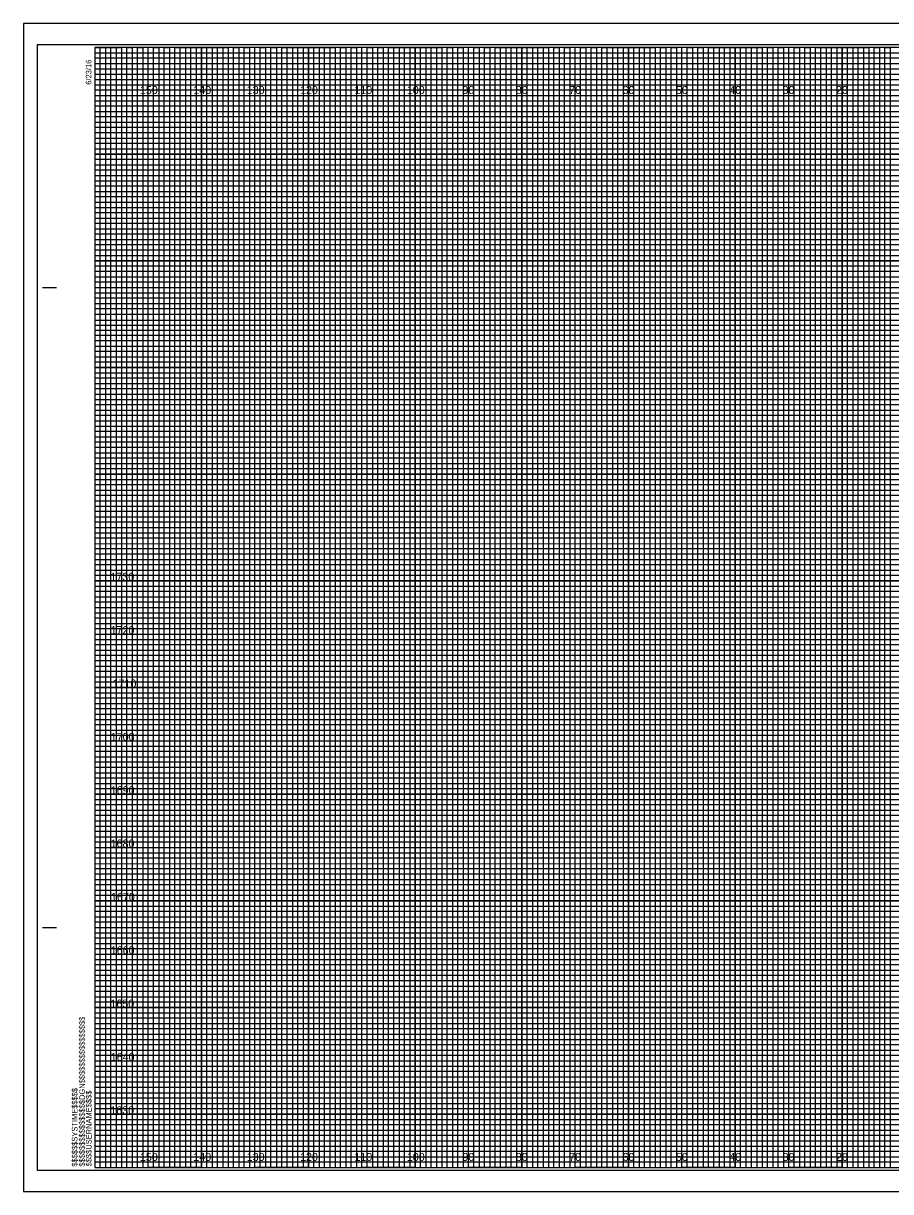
# Model space of a CAD drawing. Extents: x -3334 to 0, y 84 to 12624.
# Drawn here: x -336.5 to -174, y 84.2 to 303.2 of the extents above; entities that cross this region are included whole.
import ezdxf

# ---------------------------------------------------------------- set-up
doc = ezdxf.new("R2010")
doc.units = 0
for name, color, linetype in [('Old_Level_62', 7, 'Continuous'), ('Pattern 1', 7, 'Continuous'), ('Pattern 18', 7, 'Continuous'), ('Pattern 4', 7, 'Continuous'), ('Pattern 5', 7, 'Continuous'), ('Prop Dimension', 7, 'Continuous'), ('Prop Horizontal Alignment', 7, 'Continuous'), ('Raster_Level_0', 7, 'Continuous'), ('Scratch_Level_0', 7, 'Continuous'), ('Scratch_Level_3', 7, 'Continuous'), ('Scratch_Level_5', 7, 'Continuous')]:
    doc.layers.add(name, color=color, linetype=linetype)

msp = doc.modelspace()

# ---------------------------------------------------------------- linework, layer by layer
at = {"layer": 'Old_Level_62'}
for p, q in [((-332.92, 253.67), (-330.42, 253.67)), ((-332.82, 253.67), (-330.32, 253.67)), ((-332.92, 133.67), (-330.42, 133.67)), ((-332.82, 133.67), (-330.32, 133.67)), ((-323.12, 88.67), (-323.12, 88.67)), ((-323.12, 88.67), (-323.12, 88.67)), ((-323.12, 88.67), (-323.12, 88.67)), ((-323.12, 88.67), (-323.12, 88.67)), ((-323.12, 88.67), (-323.12, 88.67)), ((-323.12, 88.67), (-323.12, 88.67)), ((-323.12, 88.67), (-323.12, 88.67))]:
    msp.add_line(p, q, dxfattribs=at)
msp.add_lwpolyline([(-3.12, 298.67), (-323.12, 298.67), (-323.12, 88.67), (-3.12, 88.67)], close=True, dxfattribs=at)
at = {"layer": 'Pattern 18'}
msp.add_lwpolyline([(-336.52, 84.17), (0.18, 84.17), (0.18, 303.17), (-336.52, 303.17)], close=True, dxfattribs=at)
at = {"layer": 'Pattern 4'}
for p, q in [((-323.12, 297.67), (-63.12, 297.67)), ((-63.12, 296.65), (-323.12, 296.65)), ((-323.12, 296.65), (-323.12, 295.67)), ((-323.12, 295.67), (-63.12, 295.67)), ((-63.12, 294.56), (-323.12, 294.56)), ((-323.12, 294.56), (-323.12, 292.67)), ((-323.12, 292.67), (-3.12, 292.67))]:
    msp.add_line(p, q, dxfattribs=at)
for points in [[(-323.12, 291.67), (-53.12, 291.67), (-3.12, 291.67), (-3.12, 290.67), (-323.12, 290.67)], [(-323.12, 289.67), (-3.12, 289.67), (-3.12, 287.67), (-323.12, 287.67)], [(-323.12, 286.67), (-3.12, 286.67), (-3.12, 285.67), (-323.12, 285.65)], [(-323.12, 284.67), (-3.12, 284.67), (-3.12, 282.67), (-323.12, 282.67)], [(-323.12, 281.67), (-3.12, 281.67), (-3.12, 280.67), (-323.12, 280.67)], [(-323.12, 279.67), (-3.12, 279.67), (-3.12, 277.67), (-323.12, 277.67)], [(-323.12, 276.67), (-3.12, 276.67), (-3.12, 275.67), (-323.12, 275.67)], [(-323.12, 274.67), (-3.12, 274.67), (-3.12, 272.67), (-323.12, 272.67)], [(-323.12, 271.67), (-3.12, 271.67), (-3.12, 270.67), (-323.12, 270.67)], [(-323.12, 269.67), (-3.12, 269.67), (-3.12, 267.67), (-323.12, 267.67)], [(-323.12, 266.67), (-3.12, 266.67), (-3.12, 265.67), (-323.12, 265.67)], [(-323.12, 264.67), (-3.12, 264.67), (-3.12, 262.62), (-3.12, 261.67), (-3.12, 260.67), (-323.12, 260.67)], [(-323.12, 262.67), (-3.12, 262.67), (-3.12, 261.67), (-323.12, 261.67)], [(-323.12, 259.67), (-3.12, 259.67), (-3.12, 257.67), (-323.12, 257.7)], [(-323.12, 257.7), (-3.12, 257.67), (-3.12, 256.67), (-323.12, 256.67)], [(-323.12, 255.67), (-3.12, 255.67), (-3.12, 254.67), (-323.12, 254.67)], [(-323.12, 252.67), (-3.12, 252.67), (-3.12, 251.67), (-323.12, 251.67)], [(-323.12, 250.67), (-3.12, 250.67), (-3.12, 249.67), (-323.12, 249.67)], [(-323.19, 247.56), (-3.12, 247.56), (-3.12, 246.55), (-323.19, 246.55)], [(-323.12, 245.67), (-3.12, 245.67), (-3.12, 244.67), (-323.12, 244.67)], [(-323.12, 242.67), (-3.12, 242.67), (-3.12, 241.67), (-323.12, 241.67)], [(-323.12, 240.67), (-3.12, 240.67), (-3.12, 239.67), (-323.12, 239.67)], [(-323.12, 237.67), (-3.12, 237.67), (-3.12, 236.67), (-323.12, 236.67)], [(-323.12, 235.67), (-3.12, 235.67), (-3.12, 234.67), (-323.12, 234.67)], [(-323.12, 232.67), (-3.12, 232.67), (-3.12, 231.67), (-323.12, 231.67)], [(-323.12, 230.67), (-3.12, 230.67), (-3.12, 229.67), (-323.12, 229.67)], [(-323.12, 227.67), (-3.12, 227.67), (-3.13, 226.65), (-323.12, 226.67)], [(-323.12, 225.67), (-3.12, 225.67), (-3.12, 224.67), (-323.12, 224.67)], [(-323.12, 222.67), (-3.12, 222.67), (-3.12, 221.67), (-323.12, 221.67)], [(-323.12, 220.67), (-3.12, 220.67), (-3.12, 219.67), (-323.12, 219.67)], [(-323.12, 217.67), (-3.12, 217.67), (-3.12, 216.67), (-323.12, 216.67)], [(-323.12, 215.67), (-3.12, 215.67), (-3.12, 214.67), (-323.12, 214.67)], [(-323.12, 212.67), (-3.12, 212.67), (-3.12, 211.67), (-323.12, 211.67)], [(-323.12, 210.67), (-3.12, 210.67), (-3.12, 209.67), (-323.12, 209.67)], [(-323.12, 207.67), (-3.12, 207.67), (-3.12, 206.67), (-323.12, 206.67)], [(-323.12, 205.66), (-3.05, 205.58), (-3.12, 204.67), (-323.12, 204.67)], [(-323.12, 202.67), (-3.12, 202.67), (-3.12, 201.67), (-323.12, 201.67)], [(-323.12, 200.67), (-3.12, 200.67), (-3.12, 199.67), (-323.12, 199.67)], [(-323.12, 197.67), (-3.12, 197.67), (-3.12, 196.67), (-323.12, 196.67)], [(-323.12, 195.67), (-3.12, 195.67), (-3.12, 194.67), (-323.12, 194.67)], [(-323.12, 192.67), (-3.12, 192.67), (-3.12, 191.67), (-323.12, 191.67)], [(-323.12, 190.67), (-3.12, 190.67), (-3.12, 189.67), (-323.12, 189.67)], [(-323.12, 187.67), (-3.12, 187.67), (-3.12, 186.67), (-323.12, 186.67)], [(-323.12, 185.67), (-3.12, 185.67), (-3.12, 184.67), (-323.12, 184.67)], [(-323.12, 182.67), (-3.12, 182.67), (-3.12, 181.67), (-323.12, 181.67)], [(-323.12, 180.67), (-3.12, 180.67), (-3.12, 179.67), (-323.12, 179.67)], [(-323.12, 177.67), (-3.12, 177.67), (-3.12, 176.67), (-323.12, 176.67)], [(-323.12, 175.67), (-3.12, 175.67), (-3.12, 174.67), (-323.12, 174.67)], [(-323.12, 172.67), (-3.12, 172.67), (-3.12, 171.67), (-323.12, 171.67)], [(-323.12, 170.67), (-3.12, 170.67), (-3.12, 169.67), (-323.12, 169.67)], [(-323.12, 167.67), (-3.12, 167.67), (-3.13, 166.65), (-323.12, 166.67)], [(-323.12, 165.67), (-3.12, 165.67), (-3.12, 164.67), (-323.12, 164.67)], [(-323.12, 162.67), (-3.12, 162.67), (-3.12, 161.67), (-323.12, 161.67)], [(-323.12, 160.67), (-3.12, 160.67), (-3.12, 159.67), (-323.12, 159.67)], [(-323.12, 157.67), (-3.12, 157.67), (-3.12, 156.67), (-323.12, 156.67)], [(-323.12, 155.67), (-3.12, 155.67), (-3.12, 154.67), (-323.12, 154.67)], [(-323.12, 152.67), (-3.12, 152.67), (-3.12, 151.67), (-323.12, 151.67)], [(-323.12, 150.67), (-3.12, 150.67), (-3.12, 149.67), (-323.12, 149.67)], [(-323.12, 147.67), (-3.12, 147.67), (-3.12, 146.67), (-323.12, 146.67)], [(-323.12, 145.66), (-3.05, 145.58), (-3.12, 144.67), (-323.12, 144.67)], [(-323.12, 142.67), (-3.12, 142.67), (-3.12, 141.67), (-323.12, 141.67)], [(-323.12, 140.67), (-3.12, 140.67), (-3.12, 139.67), (-323.12, 139.67)], [(-323.12, 137.67), (-3.12, 137.67), (-3.12, 136.67), (-323.12, 136.67)], [(-323.12, 135.67), (-3.12, 135.67), (-3.12, 134.67), (-323.12, 134.67)], [(-323.12, 132.67), (-3.12, 132.67), (-3.12, 131.67), (-323.12, 131.67)], [(-323.12, 130.67), (-3.12, 130.67), (-3.12, 129.67), (-323.12, 129.67)], [(-323.12, 127.67), (-3.12, 127.67), (-3.12, 126.67), (-323.12, 126.67)], [(-323.12, 125.67), (-3.12, 125.67), (-3.12, 124.67), (-323.12, 124.67)], [(-323.12, 122.67), (-3.12, 122.67), (-3.12, 121.67), (-323.12, 121.67)], [(-323.12, 120.67), (-3.12, 120.67), (-3.12, 119.67), (-323.12, 119.67)], [(-323.12, 117.67), (-3.12, 117.67), (-3.12, 116.67), (-323.12, 116.67)], [(-323.12, 115.67), (-3.12, 115.67), (-3.12, 114.67), (-323.12, 114.67)], [(-323.12, 112.67), (-3.12, 112.67), (-3.12, 111.67), (-323.12, 111.67)], [(-323.12, 110.67), (-3.12, 110.67), (-3.12, 109.67), (-323.12, 109.67)], [(-323.12, 107.67), (-3.12, 107.67), (-3.12, 106.67), (-323.12, 106.67)], [(-323.12, 105.67), (-3.12, 105.67), (-3.12, 104.67), (-323.12, 104.67)], [(-323.12, 102.67), (-3.12, 102.67), (-3.12, 101.67), (-323.12, 101.67)], [(-323.12, 100.67), (-3.12, 100.67), (-3.12, 99.67), (-323.12, 99.67)], [(-323.12, 97.67), (-3.12, 97.67), (-3.12, 96.67), (-323.12, 96.67)], [(-323.12, 95.67), (-3.12, 95.67), (-3.12, 94.67), (-323.12, 94.67)], [(-323.12, 92.67), (-3.12, 92.67), (-3.12, 91.67), (-323.12, 91.67)], [(-323.12, 90.67), (-3.12, 90.67), (-3.12, 89.67), (-323.12, 89.67)]]:
    msp.add_lwpolyline(points, dxfattribs=at)
at = {"layer": 'Pattern 5'}
for p, q in [((0.18, 303.17), (-336.52, 303.17)), ((-336.52, 303.17), (-336.52, 84.17)), ((-336.52, 84.17), (0.18, 84.17))]:
    msp.add_line(p, q, dxfattribs=at)
at = {"layer": 'Prop Dimension'}
for points in [[(-323.12, 88.67), (-322.12, 88.67), (-322.12, 298.67), (-321.12, 298.67), (-321.12, 88.67)], [(-321.12, 88.67), (-320.12, 88.67), (-320.12, 298.67), (-319.12, 298.67), (-319.12, 88.67)], [(-318.12, 88.67), (-317.12, 88.67), (-317.12, 298.67), (-316.12, 298.67), (-316.12, 88.67)], [(-316.12, 88.67), (-315.12, 88.67), (-315.12, 298.67), (-314.12, 298.67), (-314.12, 88.67)], [(-313.12, 88.67), (-312.12, 88.67), (-312.12, 298.67), (-311.12, 298.67), (-311.12, 88.67)], [(-311.12, 88.67), (-310.12, 88.67), (-310.12, 298.67), (-309.12, 298.67), (-309.12, 88.67)], [(-308.12, 88.67), (-307.12, 88.67), (-307.12, 298.67), (-306.12, 298.67), (-306.12, 88.67)], [(-306.12, 88.67), (-305.12, 88.67), (-305.12, 298.67), (-304.12, 298.67), (-304.12, 88.67)], [(-303.12, 88.67), (-302.12, 88.67), (-302.12, 298.67), (-301.12, 298.67), (-301.12, 88.67)], [(-301.12, 88.67), (-300.12, 88.67), (-300.12, 298.67), (-299.12, 298.67), (-299.12, 88.67)], [(-298.12, 88.67), (-297.12, 88.67), (-297.12, 298.67), (-296.12, 298.67), (-296.12, 88.67)], [(-296.12, 88.67), (-295.12, 88.67), (-295.12, 298.67), (-294.12, 298.67), (-294.12, 88.67)], [(-293.12, 88.67), (-292.12, 88.67), (-292.12, 298.67), (-291.12, 298.67), (-291.12, 88.67)], [(-291.12, 88.67), (-290.12, 88.67), (-290.12, 298.67), (-289.12, 298.67), (-289.12, 88.67)], [(-288.12, 88.67), (-287.12, 88.67), (-287.12, 298.67), (-286.12, 298.67), (-286.12, 88.67)], [(-286.12, 88.67), (-285.12, 88.67), (-285.12, 298.67), (-284.12, 298.67), (-284.12, 88.67)], [(-283.12, 88.67), (-282.12, 88.67), (-282.12, 298.67), (-281.12, 298.67), (-281.12, 88.67)], [(-281.12, 88.67), (-280.12, 88.67), (-280.12, 298.67), (-279.12, 298.67), (-279.12, 88.67)], [(-278.12, 88.67), (-277.12, 88.67), (-277.12, 298.67), (-276.12, 298.67), (-276.12, 88.67)], [(-276.12, 88.67), (-275.12, 88.67), (-275.12, 298.67), (-274.12, 298.67), (-274.12, 88.67)], [(-273.12, 88.67), (-272.12, 88.67), (-272.12, 298.67), (-271.12, 298.67), (-271.12, 88.67)], [(-271.12, 88.67), (-270.12, 88.67), (-270.12, 298.67), (-269.12, 298.67), (-269.12, 88.67)], [(-268.12, 88.67), (-267.12, 88.67), (-267.12, 298.67), (-266.12, 298.67), (-266.12, 88.67)], [(-266.12, 88.67), (-265.12, 88.67), (-265.12, 298.67), (-264.12, 298.67), (-264.12, 88.67)], [(-263.12, 88.67), (-262.12, 88.67), (-262.12, 298.67), (-261.12, 298.67), (-261.12, 88.67)], [(-261.12, 88.67), (-260.12, 88.67), (-260.12, 298.67), (-259.12, 298.67), (-259.12, 88.67)], [(-258.12, 88.67), (-257.12, 88.67), (-257.12, 298.67), (-256.12, 298.67), (-256.12, 88.67)], [(-256.12, 88.67), (-255.12, 88.67), (-255.12, 298.67), (-254.12, 298.67), (-254.12, 88.67)], [(-253.12, 88.67), (-252.12, 88.67), (-252.12, 298.67), (-251.12, 298.67), (-251.12, 88.67)], [(-251.12, 88.67), (-250.12, 88.67), (-250.12, 298.67), (-249.12, 298.67), (-249.12, 88.67)], [(-248.12, 88.67), (-247.12, 88.67), (-247.12, 298.67), (-246.12, 298.67), (-246.12, 88.67)], [(-246.12, 88.67), (-245.12, 88.67), (-245.12, 298.67), (-244.12, 298.67), (-244.12, 88.67)], [(-243.12, 88.67), (-242.12, 88.67), (-242.12, 298.67), (-241.12, 298.67), (-241.12, 88.67)], [(-241.12, 88.67), (-240.12, 88.67), (-240.12, 298.67), (-239.12, 298.67), (-239.12, 88.67)], [(-238.12, 88.67), (-237.12, 88.67), (-237.12, 298.67), (-236.12, 298.67), (-236.12, 88.67)], [(-236.12, 88.67), (-235.12, 88.67), (-235.12, 298.67), (-234.12, 298.67), (-234.12, 88.67)], [(-233.12, 88.67), (-232.12, 88.67), (-232.12, 298.67), (-231.12, 298.67), (-231.12, 88.67)], [(-231.12, 88.67), (-230.12, 88.67), (-230.12, 298.67), (-229.12, 298.67), (-229.12, 88.67)], [(-228.12, 88.67), (-227.12, 88.67), (-227.12, 298.67), (-226.12, 298.67), (-226.12, 88.67)], [(-226.12, 88.67), (-225.12, 88.67), (-225.12, 298.67), (-224.12, 298.67), (-224.12, 88.67)], [(-223.12, 88.67), (-222.12, 88.67), (-222.12, 298.67), (-221.12, 298.67), (-221.12, 88.67)], [(-221.12, 88.67), (-220.12, 88.67), (-220.12, 298.67), (-219.12, 298.67), (-219.12, 88.67)], [(-218.12, 88.67), (-217.12, 88.67), (-217.12, 298.67), (-216.12, 298.67), (-216.12, 88.67)], [(-216.12, 88.67), (-215.12, 88.67), (-215.12, 298.67), (-214.12, 298.67), (-214.12, 88.67)], [(-213.12, 88.67), (-212.12, 88.67), (-212.12, 298.67), (-211.12, 298.67), (-211.12, 88.67)], [(-211.12, 88.67), (-210.12, 88.67), (-210.12, 298.67), (-209.12, 298.67), (-209.12, 88.67)], [(-208.12, 88.67), (-207.12, 88.67), (-207.12, 298.67), (-206.12, 298.67), (-206.12, 88.67)], [(-206.12, 88.67), (-205.12, 88.67), (-205.12, 298.67), (-204.12, 298.67), (-204.12, 88.67)], [(-203.12, 88.67), (-202.12, 88.67), (-202.12, 298.67), (-201.12, 298.67), (-201.12, 88.67)], [(-201.12, 88.67), (-200.12, 88.67), (-200.12, 298.67), (-199.12, 298.67), (-199.12, 88.67)], [(-198.12, 88.67), (-197.12, 88.67), (-197.12, 298.67), (-196.12, 298.67), (-196.12, 88.67)], [(-196.12, 88.67), (-195.12, 88.67), (-195.12, 298.67), (-194.12, 298.67), (-194.12, 88.67)], [(-193.12, 88.67), (-192.12, 88.67), (-192.12, 298.67), (-191.12, 298.67), (-191.12, 88.67)], [(-191.12, 88.67), (-190.12, 88.67), (-190.12, 298.67), (-189.12, 298.67), (-189.12, 88.67)], [(-188.12, 88.67), (-187.12, 88.67), (-187.12, 298.67), (-186.12, 298.67), (-186.12, 88.67)], [(-186.12, 88.67), (-185.12, 88.67), (-185.12, 298.67), (-184.12, 298.67), (-184.12, 88.67)], [(-183.12, 88.67), (-182.12, 88.67), (-182.12, 298.67), (-181.12, 298.67), (-181.12, 88.67)], [(-181.12, 88.67), (-180.12, 88.67), (-180.12, 298.67), (-179.12, 298.67), (-179.12, 88.67)], [(-178.12, 88.67), (-177.12, 88.67), (-177.12, 298.67), (-176.12, 298.67), (-176.12, 88.67)], [(-176.12, 88.67), (-175.12, 88.67), (-175.12, 298.67), (-174.12, 298.67), (-174.12, 88.67)]]:
    msp.add_lwpolyline(points, dxfattribs=at)
at = {"layer": 'Prop Horizontal Alignment'}
for points in [[(-323.12, 298.67), (-318.12, 298.67), (-318.12, 88.67), (-308.12, 88.67), (-308.12, 298.67), (-298.12, 298.67), (-298.12, 88.67), (-288.12, 88.67), (-288.12, 298.67), (-278.12, 298.67), (-278.12, 88.67), (-268.12, 88.67), (-268.12, 298.67), (-258.12, 298.67), (-258.12, 88.67), (-248.12, 88.67), (-248.12, 298.67), (-238.12, 298.67), (-238.12, 88.67), (-228.12, 88.67), (-228.12, 298.67), (-218.12, 298.67), (-218.12, 88.67), (-208.12, 88.67), (-208.12, 298.67), (-198.12, 298.67), (-198.12, 88.67), (-188.12, 88.67), (-188.12, 298.67), (-178.12, 298.67), (-178.12, 88.67), (-168.12, 88.67)], [(-323.12, 293.67), (-48.12, 293.67)], [(-323.12, 273.67), (-3.12, 273.67), (-3.12, 283.67), (-323.12, 283.67)], [(-323.12, 253.67), (-3.12, 253.67), (-3.12, 263.67), (-323.12, 263.67)], [(-323.12, 233.67), (-3.12, 233.67), (-3.12, 243.67), (-323.12, 243.67)], [(-323.12, 213.67), (-3.12, 213.67), (-3.12, 223.67), (-323.12, 223.67)], [(-323.12, 193.67), (-3.12, 193.67), (-3.12, 203.67), (-323.12, 203.67)], [(-323.12, 173.67), (-3.12, 173.67), (-3.12, 183.67), (-323.12, 183.67)], [(-323.12, 153.67), (-3.12, 153.67), (-3.12, 163.67), (-323.12, 163.67)], [(-323.12, 133.67), (-3.12, 133.67), (-3.12, 143.67), (-323.12, 143.67)], [(-323.12, 113.67), (-3.12, 113.67), (-3.12, 123.67), (-323.12, 123.67)], [(-323.12, 93.67), (-3.12, 93.67), (-3.12, 103.67), (-323.12, 103.67)]]:
    msp.add_lwpolyline(points, dxfattribs=at)
at = {"layer": 'Scratch_Level_0'}
for p, q in [((-313.12, 88.67), (-313.12, 298.67)), ((-303.12, 88.67), (-303.12, 298.67)), ((-293.12, 88.67), (-293.12, 298.67)), ((-283.12, 88.67), (-283.12, 298.67)), ((-273.12, 88.67), (-273.12, 298.67)), ((-263.12, 88.67), (-263.12, 298.67)), ((-253.12, 88.67), (-253.12, 298.67)), ((-243.12, 88.67), (-243.12, 298.67)), ((-233.12, 88.67), (-233.12, 298.67)), ((-223.12, 88.67), (-223.12, 298.67)), ((-213.12, 88.67), (-213.12, 298.67)), ((-203.12, 88.67), (-203.12, 298.67)), ((-193.12, 88.67), (-193.12, 298.67)), ((-183.12, 88.67), (-183.12, 298.67)), ((-323.12, 288.67), (-3.12, 288.67)), ((-323.12, 278.67), (-3.12, 278.67)), ((-323.12, 268.67), (-3.12, 268.67)), ((-323.12, 258.67), (-3.12, 258.67)), ((-323.12, 248.67), (-3.12, 248.67)), ((-323.12, 238.67), (-3.12, 238.67)), ((-323.12, 228.67), (-3.12, 228.67)), ((-323.12, 218.67), (-3.12, 218.67)), ((-323.12, 208.67), (-3.12, 208.67)), ((-323.12, 198.67), (-3.12, 198.67)), ((-323.12, 188.67), (-3.12, 188.67)), ((-323.12, 178.67), (-3.12, 178.67)), ((-323.12, 168.67), (-3.12, 168.67)), ((-323.12, 158.67), (-3.12, 158.67)), ((-323.12, 148.67), (-3.12, 148.67)), ((-323.12, 138.67), (-3.12, 138.67)), ((-323.12, 128.67), (-3.12, 128.67)), ((-323.12, 118.67), (-3.12, 118.67)), ((-323.12, 108.67), (-3.12, 108.67)), ((-323.12, 98.67), (-3.12, 98.67))]:
    msp.add_line(p, q, dxfattribs=at)
at = {"layer": 'Scratch_Level_3'}
for p, q in [((-313.12, 298.67), (-323.12, 298.67)), ((-313.12, 88.67), (-313.12, 298.67)), ((-293.12, 298.67), (-303.12, 298.67)), ((-303.12, 298.67), (-303.12, 88.67)), ((-293.12, 88.67), (-293.12, 298.67)), ((-273.12, 298.67), (-283.12, 298.67)), ((-283.12, 298.67), (-283.12, 88.67)), ((-273.12, 88.67), (-273.12, 298.67)), ((-253.12, 298.67), (-263.12, 298.67)), ((-263.12, 298.67), (-263.12, 88.67)), ((-253.12, 88.67), (-253.12, 298.67)), ((-233.12, 298.67), (-243.12, 298.67)), ((-243.12, 298.67), (-243.12, 88.67)), ((-233.12, 88.67), (-233.12, 298.67)), ((-213.12, 298.67), (-223.12, 298.67)), ((-223.12, 298.67), (-223.12, 88.67)), ((-213.12, 88.67), (-213.12, 298.67)), ((-193.12, 298.67), (-203.12, 298.67)), ((-203.12, 298.67), (-203.12, 88.67)), ((-193.12, 88.67), (-193.12, 298.67)), ((-173.12, 298.67), (-183.12, 298.67)), ((-183.12, 298.67), (-183.12, 88.67)), ((-303.12, 88.67), (-313.12, 88.67)), ((-283.12, 88.67), (-293.12, 88.67)), ((-263.12, 88.67), (-273.12, 88.67)), ((-243.12, 88.67), (-253.12, 88.67)), ((-223.12, 88.67), (-233.12, 88.67)), ((-203.12, 88.67), (-213.12, 88.67)), ((-183.12, 88.67), (-193.12, 88.67))]:
    msp.add_line(p, q, dxfattribs=at)
for points in [[(-323.12, 288.67), (-3.12, 288.67), (-3.12, 278.67), (-323.12, 278.67)], [(-323.12, 268.67), (-3.12, 268.67), (-3.12, 258.67), (-323.12, 258.67)], [(-323.12, 248.67), (-3.12, 248.67), (-3.12, 238.67), (-323.12, 238.67)], [(-323.12, 228.67), (-3.12, 228.67), (-3.12, 218.67), (-323.12, 218.67)], [(-323.12, 208.67), (-3.12, 208.67), (-3.12, 198.67), (-323.12, 198.67)], [(-323.12, 188.67), (-3.12, 188.67), (-3.12, 178.67), (-323.12, 178.67)], [(-323.12, 168.67), (-3.12, 168.67), (-3.12, 158.67), (-323.12, 158.67)], [(-323.12, 148.67), (-3.12, 148.67), (-3.12, 138.67), (-323.12, 138.67)], [(-323.12, 128.67), (-3.12, 128.67), (-3.12, 118.67), (-323.12, 118.67)], [(-323.12, 108.67), (-3.12, 108.67), (-3.12, 98.67), (-323.12, 98.67)]]:
    msp.add_lwpolyline(points, dxfattribs=at)
at = {"layer": 'Scratch_Level_5'}
msp.add_lwpolyline([(-333.92, 88.17), (-0.72, 88.17), (-0.72, 299.17), (-333.92, 299.17)], close=True, dxfattribs=at)

# ---------------------------------------------------------------- texts
at = {"layer": 'Old_Level_62'}
for s, p in [('6/23/16', (-323.77, 291.67)), ('$$$$$$$$$$$$$$$$DGN$$$$$$$$$$$$$$$$', (-325, 88.85)), ('$$$$$$SYSTIME$$$$$', (-326.38, 88.85)), ('$$$$USERNAME$$$$', (-323.74, 88.9))]:
    msp.add_text(s, height=1.05, rotation=90, dxfattribs=at).set_placement(p)
at = {"layer": 'Pattern 1'}
for s, p in [('1730', (-320.2, 198.67)), ('1720', (-320.18, 188.67)), ('1710', (-319.81, 178.67)), ('1700', (-320.14, 168.67)), ('1690', (-320.15, 158.67)), ('1680', (-320.17, 148.67)), ('1670', (-320.11, 138.67)), ('1660', (-320.15, 128.67)), ('1650', (-320.2, 118.67)), ('1640', (-320.15, 108.67)), ('1630', (-320.23, 98.67))]:
    msp.add_text(s, height=1.5, dxfattribs=at).set_placement(p)
at = {"layer": 'Raster_Level_0'}
for s, p in [('150', (-314.67, 289.92)), ('140', (-304.67, 289.92)), ('130', (-294.67, 289.92)), ('120', (-284.67, 289.92)), ('110', (-274.49, 289.92)), ('100', (-264.67, 289.92)), ('90', (-254.26, 289.92)), ('80', (-244.26, 289.92)), ('70', (-234.26, 289.92)), ('60', (-224.26, 289.92)), ('50', (-214.26, 289.92)), ('40', (-204.26, 289.92)), ('30', (-194.26, 289.92)), ('20', (-184.26, 289.92)), ('150', (-314.67, 89.92)), ('140', (-304.67, 89.92)), ('130', (-294.67, 89.92)), ('120', (-284.67, 89.92)), ('110', (-274.49, 89.92)), ('100', (-264.67, 89.92)), ('90', (-254.26, 89.92)), ('80', (-244.26, 89.92)), ('70', (-234.26, 89.92)), ('60', (-224.26, 89.92)), ('50', (-214.26, 89.92)), ('40', (-204.26, 89.92)), ('30', (-194.26, 89.92)), ('20', (-184.26, 89.92))]:
    msp.add_text(s, height=1.5, dxfattribs=at).set_placement(p)

doc.saveas('drawing.dxf')
